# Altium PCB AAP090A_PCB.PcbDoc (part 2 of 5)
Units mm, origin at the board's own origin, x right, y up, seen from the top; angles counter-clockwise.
Board outline 160 x 130 mm, 4 copper layers (Top Layer, Signal Layer 1, Signal Layer 2, Bottom Layer), stack 1.567 mm thick; 507 components, 275 nets, 1462 pads, 1041 vias.
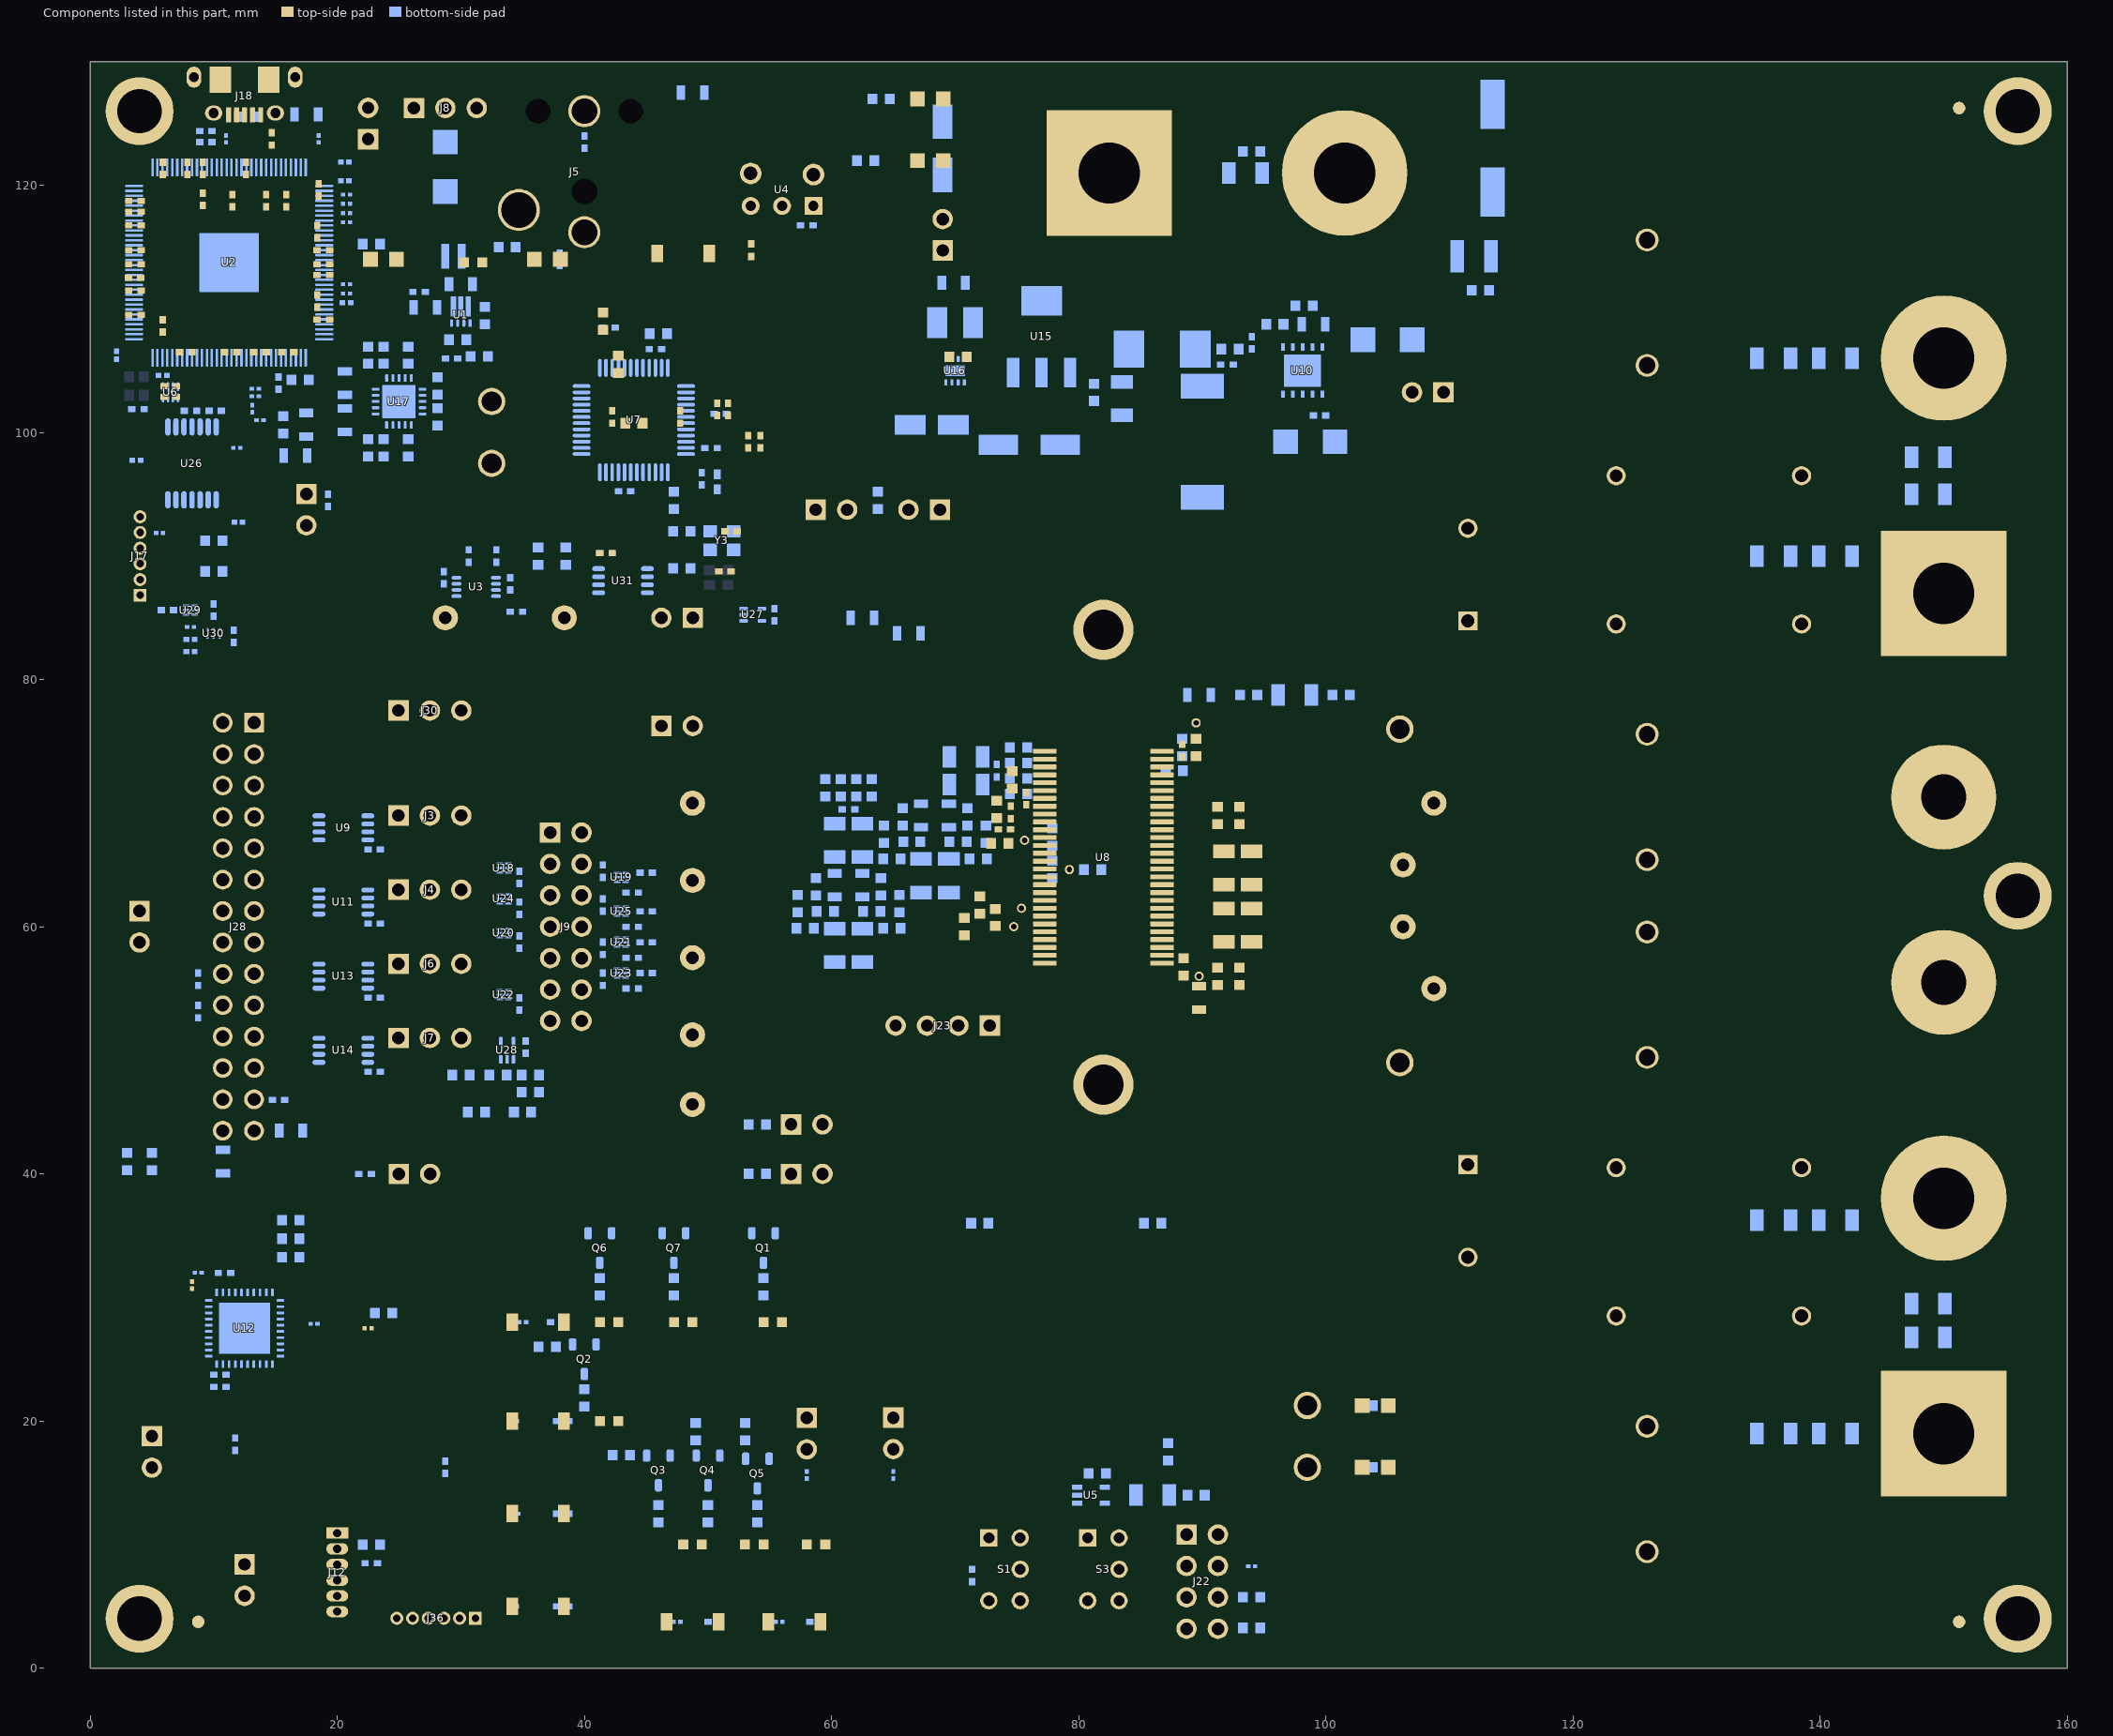
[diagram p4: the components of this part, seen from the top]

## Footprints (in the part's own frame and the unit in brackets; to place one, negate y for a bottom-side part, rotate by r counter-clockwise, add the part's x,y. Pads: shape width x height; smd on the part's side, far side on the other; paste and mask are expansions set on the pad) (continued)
DKQ0056A [mm] "SOP, 56-Leads, Body 18.415x7.49mm, Pitch 0.635mm"
  rrect25% 1.9x0.4 smd: 1(-4.75,8.572) 2(-4.75,7.938) 3(-4.75,7.302) 4(-4.75,6.667) 5(-4.75,6.032) 6(-4.75,5.397) 7(-4.75,4.763) 8(-4.75,4.127) 9(-4.75,3.492) 10(-4.75,2.857) 11(-4.75,2.222) 12(-4.75,1.587) 13(-4.75,0.953) 14(-4.75,0.318) 15(-4.75,-0.318) 16(-4.75,-0.953) 17(-4.75,-1.587) 18(-4.75,-2.222) 19(-4.75,-2.857) 20(-4.75,-3.492) 21(-4.75,-4.127) 22(-4.75,-4.763) 23(-4.75,-5.397) 24(-4.75,-6.032) 25(-4.75,-6.667) 26(-4.75,-7.302) 27(-4.75,-7.938) 28(-4.75,-8.572) 29(4.75,-8.572) 30(4.75,-7.938) 31(4.75,-7.302) 32(4.75,-6.667) 33(4.75,-6.032) 34(4.75,-5.397) 35(4.75,-4.763) 36(4.75,-4.127) 37(4.75,-3.492) 38(4.75,-2.857) 39(4.75,-2.222) 40(4.75,-1.587) 41(4.75,-0.953) 42(4.75,-0.318) 43(4.75,0.318) 44(4.75,0.953) 45(4.75,1.587) 46(4.75,2.222) 47(4.75,2.857) 48(4.75,3.492) 49(4.75,4.127) 50(4.75,4.763) 51(4.75,5.397) 52(4.75,6.032) 53(4.75,6.667) 54(4.75,7.302) 55(4.75,7.938) 56(4.75,8.572)
  silkscreen extent -5.55,-9.2 3.74,9.2, body extent -5.19,-9.21 5.19,9.21, height 2.3
DQM0008A [mm] "TI"
  rrect50% 0.7x0.2 smd: 1(-0.45,0.6) 2(-0.45,0.2) 3(-0.45,-0.2) 4(-0.45,-0.6) 5(0.45,-0.6) 6(0.45,-0.2) 7(0.45,0.2) 8(0.45,0.6)
  silkscreen extent -0.72,-1.02 0.72,1.02, body extent -0.6,-0.9 0.6,0.9, height 0.5
DRL0005A [mm] "SOTFL, 5-Flat Leads, Body 1.2x1.6x0.6mm, Pitch 0.5mm, TI recommended"
  rrect33% 0.67x0.3 smd: 1(-0.74,0.5) 2(-0.74,0) 3(-0.74,-0.5) 4(0.74,-0.5) 5(0.74,0.5)
  silkscreen extent -0.9,-0.95 0.5,0.95, body extent -0.85,-0.85 0.85,0.85, height 0.62
DRY0006A [mm] "PSON, 6-Leads, Body 1x1.45mm, Pitch 0.5mm, TI Recommended"
  rect 0.35x0.2 smd: 1(-0.275,0.5)
  rect 0.3x0.2 smd: 2(-0.3,0) 3(-0.3,-0.5) 4(0.3,-0.5) 5(0.3,0) 6(0.3,0.5)
  silkscreen extent -0.5,-0.85 0.2,0.85, body extent -0.53,-0.75 0.53,0.75, height 0.61
DSF0006A [mm] "TI recommended land pattern"
  rect 0.53x0.2 smd paste-0.1 mask+0.038: 1(-0.34,0.35) 2(-0.34,0) 3(-0.34,-0.35) 4(0.34,-0.35) 5(0.34,0) 6(0.34,0.35)
  silkscreen extent -0.85,0.63 -0.75,0.72, body extent -0.52,-0.52 0.52,0.52, height 0.4
DSG0008A [mm] "SON, 8-Leads, Body 2x2mm, Pitch 0.5mm, Thermal Pad 1.6x0.9mm, TI Recommended"
  rrect40% 0.5x0.25 smd: 1(-0.95,0.75) 2(-0.95,0.25) 3(-0.95,-0.25) 4(-0.95,-0.75) 5(0.95,-0.75) 6(0.95,-0.25) 7(0.95,0.25) 8(0.95,0.75)
  rrect11% 0.9x1.6 smd paste-0.45: 9(0,0)
  silkscreen extent -1.07,-1.15 1.07,1.15, body extent -1.05,-1.05 1.05,1.05, height 0.8
FC_1800x3550 [mm] "TH, 2-Leads, Dia 18mm, Lead Spacing 7.5mm"
  rect 1.55x1.55 hole 1.05: 1(-3.75,0)
  round 1.55 hole 1.05: 2(3.75,0)
  silkscreen extent -9.25,-9.25 9.25,9.25, body extent -9.18,-9.23 9.22,9.24, height 37.01
FCC_disclaimer [mm]
Fiducial10-20 [mm]
  round 1 smd mask+0.5: 1(0,0)
  Top Layer keep-out circle w1.178: c0,0 r0.5
HARWIN_S1911-46R [mm] "HARWIN"
  rect 2.48x3 smd mask+0.102: 1(-2.69,0) 2(2.69,0)
  silkscreen extent -0.5,-1.5 0.5,1.5, body extent -3.42,-1.25 3.43,1.26, height 0.99
Keystone5001 [mil] "For Keystone 500x miniature loop terminals"
  round 80 hole 40: 1(0,0)
  silkscreen extent -52,-52 52,52, body extent -49,-49 49,49, height 182
Keystone5003 [mil] "For Keystone 500x miniature loop terminals"
  round 80 hole 40: 1(0,0)
  silkscreen extent -52,-52 52,52, body extent -49,-49 49,49, height 182
Keystone5010 [mil] "Keystone Multipurpose loops"
  round 87 hole 63: 1(0,0)
  silkscreen extent -70,-70 70,70, body extent -63,-63 63,62, height 319
Keystone5011 [mil] "Keystone Multipurpose loops"
  round 87 hole 63: 1(0,0)
  silkscreen extent -70,-70 70,70, body extent -63,-63 63,62, height 319
Keystone5128 [mil] "Keystone Multipurpose loops"
  round 87 hole 63: 1(0,0)
  silkscreen extent -70,-70 70,70, body extent -63,-63 63,62, height 319
Keystone24438 [mil] "Standoff, Aluminium, M3x0.5mm, L 25 mm"
  round 1 on Mech4: 0(0,0)
  body extent -98,-114 98,114, height 984
Keystone_971 [mm] "PC Mount Phono Jack-Red, TH"
  round 2.6 hole 2.08: 1(0,0) 3(9.8,0)
  round 3.4 hole 2.87: 4(8,-5.3)
  round 0 hole 1.98 unplated: M1(0,3.745) M2(0,-3.745)
  round 0 hole 2.08 unplated: M3(6.5,0)
  silkscreen extent -3.99,-5.01 10.03,5.01, body extent -13.31,-5.44 10.05,5, height 13.02
Keystone_7007 [mm] "KEYSTONE"
  round 8.5 hole 3.658: 1(0,0)
  silkscreen extent -4.8,-4.8 4.8,4.8, body extent -5.71,-5.66 5.67,5.72, height 26.48
"LB Q39G_BLUE" [mm] "OSRAM"
  rect 0.8x0.8 smd: 1(-0.75,0) 2(0.75,0)
  silkscreen extent 1.3,-0.5 1.52,0.5, body extent -0.85,-0.45 0.85,0.45, height 0.4
LED_LTST-C170_Red [mm] "LITE-ON"
  rect 1.2x1.2 smd: 1(-1.05,0) 2(1.05,0)
  silkscreen extent -1.6,-1 2.2,1, body extent -1.05,-0.67 1.05,0.67, height 1.1
LED_LTST-C171 [mm] "LITE-ON"
  rect 1.2x1.2 smd: 1(-1.05,0) 2(1.05,0)
  silkscreen extent -1.6,-1 2.2,1, body extent -1.05,-0.67 1.05,0.67, height 0.8
LED_LTST-C190_Red [mm] "Lite-On"
  rect 0.8x0.8 smd: 1(-0.75,0) 2(0.75,0)
  silkscreen extent -1.1,-0.8 1.8,0.8, body extent -0.85,-0.45 0.85,0.45, height 0.9
LTST-C170KFKT_Orange [mm] "LITE-ON"
  rect 1.2x1.2 smd: 1(-1.05,0) 2(1.05,0)
  silkscreen extent -1.6,-1 2.2,1, body extent -1.05,-0.67 1.05,0.67, height 1.1
LTST-C170TBKT_Blue [mm] "LITE-ON"
  rect 1.2x1.2 smd: 1(-1.05,0) 2(1.05,0)
  silkscreen extent -1.6,-1 2.2,1, body extent -1.05,-0.67 1.05,0.67, height 1.2
MA5173 [mm] "TH, 2-Leads, Body 28.6x12.3mm, Pin Spacing 10.15mm"
  round 1.85 hole 1.35: 1(-5.075,0) 2(5.075,0)
  silkscreen extent -6.15,-14.3 6.15,14.3, body extent -6.15,-14.3 6.15,14.3, height 28.6
Mill-Max_851-XX-006-10-001000 [mil] "Mill-Max"
  rect 36x70 hole 26: 1(125,0)
  oval 36x70 hole 26: 2(75,0) 3(25,0) 4(-25,0) 5(-75,0) 6(-125,0)
  silkscreen extent -162,-50 177,50, body extent -160,-45 160,45, height 162
MP04A_N [mm] "SOT223, 4-Leads, Body 6.5x3.5mm, Pitch 2.3mm, Lead Span 7mm, IPC Medium Density"
  rect 2.4x1 smd: 1(-2.9,2.3) 2(-2.9,0) 3(-2.9,-2.3)
  rect 2.4x3.3 smd: 4(2.9,0)
  silkscreen extent -3.02,-3.35 1.4,3.48, body extent -1.85,-3.35 1.85,3.35, height 1.8
Pb-Free_Overlay_Medium [mm]
  silkscreen extent -2.41,-2.41 2.41,2.41
PBC03SAAN [mm] "Sullins 100mil, 1x3, 230 mil above insulator"
  rect 1.65x1.65 hole 1.016: 1(-2.54,0)
  round 1.65 hole 1.016: 2(0,0) 3(2.54,0)
  silkscreen extent -3.81,-1.27 3.81,1.27, body extent -3.81,-1.27 3.81,1.27, height 8.38
PFB0048A_N [mm] "Thin QFP, 48-Leads, Body 7x7mm, Pitch 0.5mm, IPC Medium Density"
  oval 1.45x0.3 smd: 1(-4.225,2.75) 2(-4.225,2.25) 3(-4.225,1.75) 4(-4.225,1.25) 5(-4.225,0.75) 6(-4.225,0.25) 7(-4.225,-0.25) 8(-4.225,-0.75) 9(-4.225,-1.25) 10(-4.225,-1.75) 11(-4.225,-2.25) 12(-4.225,-2.75) 25(4.225,-2.75) 26(4.225,-2.25) 27(4.225,-1.75) 28(4.225,-1.25) 29(4.225,-0.75) 30(4.225,-0.25) 31(4.225,0.25) 32(4.225,0.75) 33(4.225,1.25) 34(4.225,1.75) 35(4.225,2.25) 36(4.225,2.75)
  oval 0.3x1.45 smd: 13(-2.75,-4.225) 14(-2.25,-4.225) 15(-1.75,-4.225) 16(-1.25,-4.225) 17(-0.75,-4.225) 18(-0.25,-4.225) 19(0.25,-4.225) 20(0.75,-4.225) 21(1.25,-4.225) 22(1.75,-4.225) 23(2.25,-4.225) 24(2.75,-4.225) 37(2.75,4.225) 38(2.25,4.225) 39(1.75,4.225) 40(1.25,4.225) 41(0.75,4.225) 42(0.25,4.225) 43(-0.25,4.225) 44(-0.75,4.225) 45(-1.25,4.225) 46(-1.75,4.225) 47(-2.25,4.225) 48(-2.75,4.225)
  silkscreen extent -4.17,-2.75 2.75,3.57, body extent -4.5,-4.5 4.5,4.5, height 1.07
PLR135_T10 [mm] "EVERLIGHT"
  rect 1.45x1.45 hole 0.813: 1(2.54,-4.67)
  round 1.45 hole 0.813: 2(0,-4.67) 3(-2.54,-4.67)
  round 1.75 hole 1.092: 4(2.54,-2.13) 5(-2.54,-2.04)
  silkscreen extent -5.05,-6.93 5.05,6.95, body extent -5,-6.9 5,6.9, height 10.3
Pomona_6883 [mil] "Dual Binding Posts with Base, 2x1, TH"
  rect 400x400 hole 195: 1(-375,0)
  round 400 hole 195: 2(375,0)
  silkscreen extent -690,-344 690,315, body extent -690,-315 690,315, height 1354
PW0014A_N [mm] "TSOP, 14-Leads, Body 5x4.4mm, Pitch 0.65mm, IPC Medium Density"
  oval 1.4x0.45 smd: 1(-2.95,1.95) 2(-2.95,1.3) 3(-2.95,0.65) 4(-2.95,0) 5(-2.95,-0.65) 6(-2.95,-1.3) 7(-2.95,-1.95) 8(2.95,-1.95) 9(2.95,-1.3) 10(2.95,-0.65) 11(2.95,0) 12(2.95,0.65) 13(2.95,1.3) 14(2.95,1.95)
  silkscreen extent -3.4,-2.55 1.85,2.55, body extent -3.21,-2.5 3.21,2.5, height 1
RHA0040B [mm] "QFN, 40-Leads, Body 6x6mm, Pitch 0.5mm, Thermal Pad 4.15 x 4.15mm, TI Recommended"
  rrect45% 0.6x0.22 smd mask+0.07: 1(-2.9,2.25) 2(-2.9,1.75) 3(-2.9,1.25) 4(-2.9,0.75) 5(-2.9,0.25) 6(-2.9,-0.25) 7(-2.9,-0.75) 8(-2.9,-1.25) 9(-2.9,-1.75) 10(-2.9,-2.25) 21(2.9,-2.25) 22(2.9,-1.75) 23(2.9,-1.25) 24(2.9,-0.75) 25(2.9,-0.25) 26(2.9,0.25) 27(2.9,0.75) 28(2.9,1.25) 29(2.9,1.75) 30(2.9,2.25)
  rrect45% 0.22x0.6 smd mask+0.07: 11(-2.25,-2.9) 12(-1.75,-2.9) 13(-1.25,-2.9) 14(-0.75,-2.9) 15(-0.25,-2.9) 16(0.25,-2.9) 17(0.75,-2.9) 18(1.25,-2.9) 19(1.75,-2.9) 20(2.25,-2.9) 31(2.25,2.9) 32(1.75,2.9) 33(1.25,2.9) 34(0.75,2.9) 35(0.25,2.9) 36(-0.25,2.9) 37(-0.75,2.9) 38(-1.25,2.9) 39(-1.75,2.9) 40(-2.25,2.9)
  rrect9% 1.17x1.17 on Bottom Paste: 41(-1.37,-1.37) 41(-1.37,0) 41(-1.37,1.37) 41(0,-1.37) 41(0,0) 41(0,1.37) 41(1.37,-1.37) 41(1.37,0) 41(1.37,1.37)
  rrect2% 4.15x4.15 smd paste-2.1: 41(0,0)
  silkscreen extent -3.22,-3.22 3.22,3.22, body extent -3,-3 3,3, height 1
RLT0007A [mm] "TI"
  rect 0.6x0.25 smd paste-0.2: 1(-0.9,0.75)
  oval 0.6x0.25 smd paste-0.2: 2(-0.9,0.25) 3(-0.9,-0.25) 4(-0.9,-0.75)
  rect 1.64x0.44 smd paste-0.22 mask-0.07: 5(0.45,-0.6) 6(0.45,0) 7(0.45,0.6)
  silkscreen extent -1.1,-1.15 1.1,1.15, body extent -1,-1 1,1, height 1
RTJ0020D [mm] "QFN, 20-Leads, Body 4x4mm, Pitch 0.5mm, Thermal Pad 2.7x2.7mm, TI Recommended"
  rrect42% 0.6x0.24 smd: 1(-1.9,1) 2(-1.9,0.5) 3(-1.9,0) 4(-1.9,-0.5) 5(-1.9,-1) 11(1.9,-1) 12(1.9,-0.5) 13(1.9,0) 14(1.9,0.5) 15(1.9,1)
  rrect42% 0.24x0.6 smd: 6(-1,-1.9) 7(-0.5,-1.9) 8(0,-1.9) 9(0.5,-1.9) 10(1,-1.9) 16(1,1.9) 17(0.5,1.9) 18(0,1.9) 19(-0.5,1.9) 20(-1,1.9)
  rrect8% 1.19x1.19 on Bottom Paste: 21(-0.695,-0.695) 21(-0.695,0.695) 21(0.695,-0.695) 21(0.695,0.695)
  rrect4% 2.7x2.7 smd paste-1.4: 21(0,0)
  silkscreen extent -2.22,-2.22 2.23,2.22, body extent -2.07,-2.07 2.08,2.08, height 0.8
SDC10A [mm] "SON, 10-Leads, Body 4x4 mm, Pitch 0.8mm, NSC Recommended"
  rect 0.6x0.3 smd paste-0.15 mask+0.051: 1(-1.9,1.6) 2(-1.9,0.8) 3(-1.9,0) 4(-1.9,-0.8) 5(-1.9,-1.6) 6(1.9,-1.6) 7(1.9,-0.8) 8(1.9,0) 9(1.9,0.8) 10(1.9,1.6)
  rect 2.6x3 smd paste-1.3 mask+0.051: 11(0,0)
  silkscreen extent -3.02,-2.2 2.35,2.23, body extent -2.05,-2.05 2.05,2.05, height 0.8
SM_RADIAL_B [mm] "4 x 5.8mm:  Panasonic B"
  rect 2.5x1.6 smd: 1(-1.75,0) 2(1.75,0)
  silkscreen extent -2.24,-2.25 2.25,2.25, body extent -2.25,-2.25 2.25,2.25, height 6.1
SM_RADIAL_C [mm] "5 x 5.8mm:  Panasonic C"
  rect 2.8x1.6 smd: 1(-2.15,0) 2(2.15,0)
  silkscreen extent -2.75,-2.75 2.75,2.75, body extent -2.75,-2.75 2.75,2.75, height 6.1
SM_RADIAL_D [mm] "6.3 x 5.8mm:  Panasonic D"
  rect 3.2x1.6 smd: 1(-2.5,0) 2(2.5,0)
  silkscreen extent -3.4,-3.4 3.4,3.4, body extent -3.4,-3.4 3.4,3.4, height 6.1
SM_RADIAL_F [mm] "8 x 10.2mm:  Panasonic F"
  rect 4x2 smd: 1(-3.55,0) 2(3.55,0)
  silkscreen extent -4.25,-4.25 4.25,4.25, body extent -4.25,-4.25 4.25,4.25, height 10.5
SMA [mm] "Molded Diode, 2-Leads, Body 4.3x2.6mm, IPC Medium Density, based on OnSemi component dimensions and land pattern"
  rect 2x2 smd: 1(-2,0) 2(2,0)
  silkscreen extent -3.66,-1.57 2.79,1.57, body extent -2.6,-1.3 2.6,1.3, height 2.42
SNT-100-BK-G#1 [mil] "Samtec STEP model"
  round 1 on Mech4: 0(0,0)
  body extent -100,-50 100,50, height 344
SNT-100-BK-G#2 [mil] "Samtec STEP model"
  round 1 on Mech3: 0(0,0)
  body extent -100,-50 100,50, height 344
SOT-23 [mm] "SOT23, 3-Leads, Body 2.9x1.3mm, Pitch 0.95mm, Lead Span 2.5mm, IPC Medium Density"
  rrect50% 1x0.6 smd: 1(-1.2,0.95) 2(-1.2,-0.95) 3(1.2,0)
  silkscreen extent -1.62,-1.5 0.7,1.5, body extent -1.16,-1.45 1.21,1.45, height 1
SULLINS_LPPB061NGCN-RC [mm] "SULLINS"
  rect 1.05x1.05 hole 0.61: 1(3.175,2.54)
  round 1.05 hole 0.61: 2(1.905,2.54) 3(0.635,2.54) 4(-0.635,2.54) 5(-1.905,2.54) 6(-3.175,2.54)
  silkscreen extent -4,-2.37 4.03,2, body extent -4,-2.36 4,2.59, height 2.16
Sullins_PBC02SAAN [mm] "Sullins 100mil, 1x2, 230 mil above insulator"
  rect 1.65x1.65 hole 1.016: 1(0,1.27)
  round 1.65 hole 1.016: 2(0,-1.27)
  silkscreen extent -1.37,-2.54 1.27,3.1, body extent -1.27,-2.54 1.27,2.54, height 8.38
SW_200USP1T1A1M2 [mm] "TH, 5-Leads, Body 7x4.5mm, Pitch 2.54mm"
  rect 1.4x1.4 hole 0.9: 1(-1.27,2.54)
  round 1.4 hole 0.9: 3(-1.27,-2.54) 4(1.27,2.54) 5(1.27,0) 6(1.27,-2.54)
  silkscreen extent -2.7,-3.63 2.38,3.63, body extent -2.37,-3.62 2.38,3.63, height 11.13
SW_TL1015AF160QG [mm] "E-Switch"
  rect 0.95x1.4 smd: 1(-2.1,0) 2(2.1,0)
  silkscreen extent -2,-1.5 2,1.5, body extent -2.3,-1.5 2.3,1.5, height 2
TI_Stacked_Overlay_Small [mm]
  silkscreen extent -10.63,-2.49 10.63,2.49
TP_H045P075 [mm] "TP_H0.45P0.75"
  round 0.75 hole 0.45: 1(0,0)
TQFP-128 [mm] "TQFP, 128-Leads, Body 14x14mm, Pitch 0.4mm"
  rrect50% 1.45x0.2 smd: 1(-7.7,6.2) 2(-7.7,5.8) 3(-7.7,5.4) 4(-7.7,5) 5(-7.7,4.6) 6(-7.7,4.2) 7(-7.7,3.8) 8(-7.7,3.4) 9(-7.7,3) 10(-7.7,2.6) 11(-7.7,2.2) 12(-7.7,1.8) 13(-7.7,1.4) 14(-7.7,1) 15(-7.7,0.6) 16(-7.7,0.2) 17(-7.7,-0.2) 18(-7.7,-0.6) 19(-7.7,-1) 20(-7.7,-1.4) 21(-7.7,-1.8) 22(-7.7,-2.2) 23(-7.7,-2.6) 24(-7.7,-3) 25(-7.7,-3.4) 26(-7.7,-3.8) 27(-7.7,-4.2) 28(-7.7,-4.6) 29(-7.7,-5) 30(-7.7,-5.4) 31(-7.7,-5.8) 32(-7.7,-6.2) 65(7.7,-6.2) 66(7.7,-5.8) 67(7.7,-5.4) 68(7.7,-5) 69(7.7,-4.6) 70(7.7,-4.2) 71(7.7,-3.8) 72(7.7,-3.4) 73(7.7,-3) 74(7.7,-2.6) 75(7.7,-2.2) 76(7.7,-1.8) 77(7.7,-1.4) 78(7.7,-1) 79(7.7,-0.6) 80(7.7,-0.2) 81(7.7,0.2) 82(7.7,0.6) 83(7.7,1) 84(7.7,1.4) 85(7.7,1.8) 86(7.7,2.2) 87(7.7,2.6) 88(7.7,3) 89(7.7,3.4) 90(7.7,3.8) 91(7.7,4.2) 92(7.7,4.6) 93(7.7,5) 94(7.7,5.4) 95(7.7,5.8) 96(7.7,6.2)
  rrect50% 0.2x1.45 smd: 33(-6.2,-7.7) 34(-5.8,-7.7) 35(-5.4,-7.7) 36(-5,-7.7) 37(-4.6,-7.7) 38(-4.2,-7.7) 39(-3.8,-7.7) 40(-3.4,-7.7) 41(-3,-7.7) 42(-2.6,-7.7) 43(-2.2,-7.7) 44(-1.8,-7.7) 45(-1.4,-7.7) 46(-1,-7.7) 47(-0.6,-7.7) 48(-0.2,-7.7) 49(0.2,-7.7) 50(0.6,-7.7) 51(1,-7.7) 52(1.4,-7.7) 53(1.8,-7.7) 54(2.2,-7.7) 55(2.6,-7.7) 56(3,-7.7) 57(3.4,-7.7) 58(3.8,-7.7) 59(4.2,-7.7) 60(4.6,-7.7) 61(5,-7.7) 62(5.4,-7.7) 63(5.8,-7.7) 64(6.2,-7.7) 97(6.2,7.7) 98(5.8,7.7) 99(5.4,7.7) 100(5,7.7) 101(4.6,7.7) 102(4.2,7.7) 103(3.8,7.7) 104(3.4,7.7) 105(3,7.7) 106(2.6,7.7) 107(2.2,7.7) 108(1.8,7.7) 109(1.4,7.7) 110(1,7.7) 111(0.6,7.7) 112(0.2,7.7) 113(-0.2,7.7) 114(-0.6,7.7) 115(-1,7.7) 116(-1.4,7.7) 117(-1.8,7.7) 118(-2.2,7.7) 119(-2.6,7.7) 120(-3,7.7) 121(-3.4,7.7) 122(-3.8,7.7) 123(-4.2,7.7) 124(-4.6,7.7) 125(-5,7.7) 126(-5.4,7.7) 127(-5.8,7.7) 128(-6.2,7.7)
  rrect2% 4.8x4.8 smd paste-4.8: 129(0,0)
  silkscreen extent -7.1,-7.1 7.1,7.1, body extent -7,-7 7,7, height 1.2
TXC_TD [mm] "SMD, 4-Leads, Body 2x2.5mm"
  rect 1x1.1 smd: 1(-0.75,0.95) 2(-0.75,-0.95) 3(0.75,-0.95) 4(0.75,0.95)
  silkscreen extent -1.74,0.89 -1.61,1.01, body extent -1.1,-1.35 1.1,1.35, height 0.81
VLCF4020 [mm] "TDK"
  rect 1.6x2.5 smd: 1(-1.45,0) 2(1.45,0)
  Top Layer region: -0.65,1.95 -1.55,1.95 -2.25,1.25 -2.25,1.15 -0.65,1.15
  Top Layer region: -0.65,-1.95 -1.55,-1.95 -2.25,-1.25 -2.25,-1.15 -0.65,-1.15
  Top Layer region: 0.65,1.95 1.55,1.95 2.25,1.25 2.25,1.15 0.65,1.15
  Top Layer region: 0.65,-1.95 1.55,-1.95 2.25,-1.25 2.25,-1.15 0.65,-1.15
  silkscreen extent -0.4,-2.1 0.4,2.1, body extent -2.05,-2.05 2.05,2.05, height 2
VLS2012ET [mm] "TDK"
  rect 0.65x2 smd: 1(-0.675,0) 2(0.675,0)
  silkscreen extent -0.15,-1.15 0.15,1.15, body extent -1.05,-1.05 1.05,1.05, height 1.2
WE-PD_1050 [mm] "WERTH"
  rect 2x3.5 smd: 1(-4.5,0) 2(4.5,0)
  silkscreen extent -5,-5 5,5, body extent -5,-5 5,5, height 4.75

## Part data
C1 C3 C92 C124 C125: "CAP, CERM, 22 µF, 10 V, +/- 20%, X7R, 0805", Cap_Case=0805, Manufacturer=MuRata, Supplier Part Number 1=81-GRM21BZ71A226ME5L, TempCo=X7R, Tolerance_%=20, Value1=Unknown, Value2=10V, ValueDisplayed=22µF
C2 C60 C71 C87 C91 C93: "CAP, CERM, 10 µF, 10 V, +/- 20%, X5R, 0603", Cap_Case=0603, Manufacturer=MuRata, TempCo=X5R, Tolerance_%=20, Value1=Unknown, Value2=10V, ValueDisplayed=10µF
C4 C63 C65 C95 C107: "CAP, CERM, 1 µF, 16 V, +/- 10%, X7R, 0603", Cap_Case=0603, Manufacturer=MuRata, Supplier Part Number 1=490-3900-1-ND, TempCo=X7R, Tolerance_%=10, Value1="0.011 ohm", Value2=16V, ValueDisplayed=1µF
C5 C8 C11 C14: "CAP, CERM, 10 µF, 16 V, +/- 10%, X7R, 1206", Cap_Case=1206, Manufacturer=MuRata, Supplier Part Number 1=490-3911-1-ND, TempCo=X7R, Tolerance_%=10, Value1=Unknown, Value2=16V, ValueDisplayed=10µF
C6 C9 C12 C15: library part GRM1885C1H221JA01D, "CAP, CERM, 220 pF, 50 V,+/- 5%, C0G/NP0, 0603", Cap_Case=0603, Manufacturer=MuRata, Supplier Part Number 1=490-1435-1-ND, TempCo=C0G/NP0, Tolerance_%=5, Value2=50V, ValueDisplayed=220pF
C7 C10 C13 C16: library part GRM1885C1H220JA01D, "CAP, CERM, 22 pF, 50 V, +/- 5%, C0G/NP0, 0603", Cap_Case=0603, Manufacturer=MuRata, Supplier Part Number 1=490-1411-1-ND, TempCo=C0G/NP0, Tolerance_%=5, Value1=Unknown, Value2=50V, ValueDisplayed=22pF
C17 C27 C37 C40 C45 C54 C58 C74 C80 C99 C100 C101 C102 C127 C128 C129 C130 C131 C132 C133 C134 C135 C136 C137 C138 C139 C140 C143 C144 C145 C146 C147 C148 C149: "CAP, CERM, 0.1uF, 16V, +/-10%, X7R, 0402", Cap_Case=0402, Manufacturer=MuRata, Supplier Part Number 1=490-3261-1-ND, TempCo=X7R, Tolerance_%=10, Value1=Unknown, Value2=16V, ValueDisplayed=0.1µF
C18 C19 C56 C59 C61 C69 C70 C72 C73 C88 C89 C90 C94 C108 C109 C110 C111 C112 C113 C114 C115 C116 C117 C118 C119 C120 C121 C122 C123 C151 C156: "CAP, CERM, 0.1 µF, 10 V, +/- 10%, X7R, 0402", Cap_Case=0402, Manufacturer=MuRata, Supplier Part Number 1=GRM155R71A104KA01D-ND, TempCo=X7R, Tolerance_%=10, Value1=Unknown, Value2=10V, ValueDisplayed=0.1µF
C20 C21: "CAP, CERM, 0.1 µF, 16 V, +/- 10%, X7R, 0603", Cap_Case=0603, Manufacturer=MuRata, Supplier Part Number 1=490-1532-1-ND, TempCo=X7R, Tolerance_%=10, Value1=Unknown, Value2=16V, ValueDisplayed=0.1µF
C22 C36 C44 C64 C84 C96: "CAP, CERM, 0.1 µF, 50 V, +/- 10%, X7R, 0603", Cap_Case=0603, Manufacturer=Kemet, Supplier Part Number 1=399-5089-1-ND, TempCo=X7R, Tolerance_%=10, Value1=Unknown, Value2=50V, ValueDisplayed=0.1µF
C23: "CAP, CERM, 2.2 µF, 100 V, +/- 10%, X7R, 1210", Cap_Case=1210, Manufacturer=Kemet, Supplier Part Number 1=399-5511-2-ND, TempCo=X7R, Tolerance_%=10, Value1=Unknown, Value2=100V, ValueDisplayed=2.2µF
C24 C126 C141: "CAP, CERM, 0.1 µF, 16 V, +/- 10%, X7R, 0402", Cap_Case=0402, Manufacturer=MuRata, Supplier Part Number 1=490-3261-1-ND, TempCo=X7R, Tolerance_%=10, Value1=Unknown, Value2=16V, ValueDisplayed=0.1µF
C25: "CAP, CERM, 0.1 µF, 100 V, +/- 10%, X7R, 0603", Cap_Case=0603, Manufacturer=MuRata, Supplier Part Number 1=490-6439-1-ND, TempCo=X7R, Tolerance_%=10, Value1=Unknown, Value2=100V, ValueDisplayed=0.1µF
C26: "CAP, CERM, 0.047 µF, 25 V, +/- 10%, X7R, 0402", Cap_Case=0402, Manufacturer=MuRata, Supplier Part Number 1=490-3254-1-ND, TempCo=X7R, Tolerance_%=10, Value1=Unknown, Value2=25V, ValueDisplayed=0.047µF
C28 C29 C32 C41 C42 C46 C97: "CAP, CERM, 1 µF, 100 V, +/- 10%, X7R, 1206", Cap_Case=2220, Manufacturer=MuRata, Supplier Part Number 1=490-3909-1-ND, TempCo=X7R, Tolerance_%=10, Value1=Unknown, Value2=100V, ValueDisplayed=1µF
C30 C43: library part EEU-FC1H222, "CAP, AL, 2200 µF, 50 V, +/- 20%, 0.023 ohm, TH", Cap_Case=18x35.5mm, Manufacturer=Panasonic, Supplier Part Number 1=P10335-ND, Tolerance_%=20, Value1="0.023 ohm", Value2=50V, ValueDisplayed=2200µF
C31: library part EEE-FK1J470P, "CAP, AL, 47 µF, 63 V, +/- 20%, 0.65 ohm, SMD", Cap_Case=F, Manufacturer=Panasonic, Supplier Part Number 1=PCE3823CT-ND, Tolerance_%=20, Value1="0.65 ohm", Value2=63V, ValueDisplayed=47µF
C33: "CAP, CERM, 0.01 µF, 100 V, +/- 10%, X7R, 0603", Cap_Case=0603, Manufacturer=AVX, Supplier Part Number 1=478-1205-1-ND, TempCo=X7R, Tolerance_%=10, Value1="0.098 ohm", Value2=100V, ValueDisplayed=0.01µF
C34: "CAP, CERM, 5600 pF, 50 V, +/- 10%, X7R, 0603", Cap_Case=0603, Manufacturer=MuRata, Supplier Part Number 1=490-1507-1-ND, TempCo=X7R, Tolerance_%=10, Value1=Unknown, Value2=50V, ValueDisplayed=5600pF
C35: "CAP, CERM, 4700 pF, 50 V, +/- 10%, X7R, 0603", Cap_Case=0603, Manufacturer=Kemet, Supplier Part Number 1=399-5337-1-ND, TempCo=X7R, Tolerance_%=10, Value1=Unknown, Value2=50V, ValueDisplayed=4700pF
C38: "CAP, CERM, 4.7 µF, 25 V, +/- 10%, X7R, 1206", Cap_Case=1206, Manufacturer=MuRata, Supplier Part Number 1=490-1809-1-ND, TempCo=X7R, Tolerance_%=10, Value1=Unknown, Value2=25V, ValueDisplayed=4.7µF
C39: library part EEE-FK1C470P, "CAP, AL, 47 µF, 16 V, +/- 20%, 0.36 ohm, SMD", Cap_Case=D, Manufacturer=Panasonic, Supplier Part Number 1=PCE3790CT-ND, Tolerance_%=20, Value1="0.36 ohm", Value2=16V, ValueDisplayed=47µF
C47 C67 C79 C81: "CAP, Film, 0.68 µF, 250 V, +/- 5%, TH", Cap_Case=18x9x17.5mm, Manufacturer="EPCOS Inc", Supplier Part Number 1=495-1299-ND, Tolerance_%=5, Value1=Unknown, Value2=250V, ValueDisplayed=0.68µF
C48 C49 C50 C51 C53 C57 C150: "CAP, CERM, 470 pF, 25 V, +/- 5%, C0G/NP0, 0402", Cap_Case=0402, Manufacturer=MuRata, Supplier Part Number 1=GRM1555C1E471JA01D-ND, TempCo=C0G/NP0, Tolerance_%=5, Value1=Unknown, Value2=25V, ValueDisplayed=470pF
C52: "CAP, CERM, 2200 pF, 16 V, +/- 10%, X7R, 0603", Cap_Case=0603, Manufacturer="Wurth Elektronik", Supplier Part Number 1=710-885012206036, TempCo=X7R, Tolerance_%=10, Value1=Unknown, Value2=16V, ValueDisplayed=2200pF
C55: "CAP, CERM, 1 µF, 6.3 V,+/- 20%, X5R, 0402", Cap_Case=0402, Manufacturer=MuRata, Supplier Part Number 1=490-10006-1-ND, TempCo=X5R, Tolerance_%=20, Value2=6.3V, ValueDisplayed=1µF
C62 C106: "CAP, CERM, 1000 pF, 50 V, +/- 5%, C0G/NP0, 0402", Cap_Case=0402, Manufacturer=MuRata, Supplier Part Number 1=490-3244-1-ND, TempCo=C0G/NP0, Tolerance_%=5, Value1=Unknown, Value2=50V, ValueDisplayed=1000pF
C66 C68 C76 C77: "CAP, CERM, 0.033 µF, 25 V, +/- 10%, X7R, 0603", Cap_Case=0603, Manufacturer=MuRata, Supplier Part Number 1=490-1521-1-ND, TempCo=X7R, Tolerance_%=10, Value1=Unknown, Value2=25V, ValueDisplayed=0.033µF
C75: "CAP, CERM, 2.2 µF, 10 V, +/- 10%, X5R, 0402", Cap_Case=0402, Manufacturer=TDK, Supplier Part Number 1=445-7392-1-ND, TempCo=X5R, Tolerance_%=10, Value1=Unknown, Value2=10V, ValueDisplayed=2.2µF
C78: "CAP, CERM, 0.047 µF, 50 V, +/- 10%, X7R, 0603", Cap_Case=0603, Manufacturer=MuRata, Supplier Part Number 1=490-3287-1-ND, TempCo=X7R, Tolerance_%=10, Value1=Unknown, Value2=50V, ValueDisplayed=0.047µF
C82: library part GRM155R71C104KA88D, "CAP, CERM, 0.1 µF, 16 V, +/- 10%, X7R, 0402", Cap_Case=0402, Manufacturer=MuRata, Supplier Part Number 1=490-3261-1-ND, TempCo=X7R, Tolerance_%=10, Value1=Unknown, Value2=16V, ValueDisplayed=0.1µF
C83: "CAP, CERM, 0.47 µF, 25 V, +/- 10%, X7R, 0603", Cap_Case=0603, Manufacturer=MuRata, Supplier Part Number 1=490-3291-1-ND, TempCo=X7R, Tolerance_%=10, Value1=Unknown, Value2=25V, ValueDisplayed=0.47µF
C85: library part EEE-FK1C100R, "CAP, AL, 10 µF, 16 V, +/- 20%, 1.35 ohm, SMD", Cap_Case=B, Manufacturer=Panasonic, Supplier Part Number 1=PCE3782CT-ND, Tolerance_%=20, Value1="1.35 ohm", Value2=16V, ValueDisplayed=10µF
C86: library part EEE-FK0J101UR, "CAP, AL, 100 µF, 6.3 V, +/- 20%, 0.7 ohm, SMD", Cap_Case=C, Manufacturer=Panasonic, Supplier Part Number 1=PCE3762CT-ND, Tolerance_%=20, Value1="0.7 ohm", Value2=6.3V, ValueDisplayed=100µF
C98 C103 C104 C105: library part GRM31CR72A105KA01L, "CAP, CERM, 1 µF, 100 V, +/- 10%, X7R, 1206", Cap_Case=2220, Manufacturer=MuRata, Supplier Part Number 1=490-3909-1-ND, TempCo=X7R, Tolerance_%=10, Value1=Unknown, Value2=100V, ValueDisplayed=1µF
C142: "CAP, CERM, 2.2 µF, 10 V, +/- 10%, X7R, 0603", Cap_Case=0603, Manufacturer=MuRata, Supplier Part Number 1=490-4520-1-ND, TempCo=X7R, Tolerance_%=10, Value1="0.009 ohm", Value2=10V, ValueDisplayed=2.2µF
C152 C153 C154 C155: library part GRM3195C1H102JA01D, "CAP, CERM, 1000 pF, 50 V, +/- 5%, C0G/NP0, 1206", Cap_Case=1206, Manufacturer=MuRata, Supplier Part Number 1=490-1749-1-ND, TempCo=C0G/NP0, Tolerance_%=5, Value1=Unknown, Value2=50V, ValueDisplayed=1000pF
D1: library part LTST-C170TBKT, "LED, Blue, SMD", Color=Blue, Manufacturer=Lite-On, Supplier Part Number 1=160-1579-1-ND, Value1=W, Value2=3.3V
D2 D5 D6 D7 D8 D15 D16: library part "LB Q39G-L2N2-35-1", "LED, Blue, SMD", Color=blue, Manufacturer=OSRAM, Supplier Part Number 1=475-2816-1-ND, Value1=W, Value2=2.85V
D3 D13 D14: library part LTST-C171GKT, "LED, Green, SMD", Color=green, Manufacturer=Lite-On, Supplier Part Number 1=160-1423-1-ND, Value1=W, Value2=2.1V
D4: library part LTST-C190CKT, "LED, Red, SMD", Color=red, Manufacturer=Lite-On, Power_TotalModule=0.0625, Supplier Part Number 1=160-1181-1-ND, Value1=0.0625W, Value2=2V
D9: library part LTST-C170KFKT, "LED, Orange, SMD", Color=orange, Manufacturer=Lite-On, Supplier Part Number 1=160-1413-1-ND, Value1=W, Value2=2V
D10: library part LTST-C170KRKT, "LED, Red, SMD", Color=red, Manufacturer=Lite-On, Supplier Part Number 1=160-1415-1-ND, Value1=W, Value2=2V
D11: "Diode, Schottky, 100 V, 3 A, SMA", Manufacturer="Micro Commercial Components", Supplier Part Number 1=SK310A-TPCT-ND, Value1=3A, Value2=0.85V
D12 D17: "Diode, Schottky, 100 V, 1 A, SMA", Manufacturer="Diodes Inc.", Supplier Part Number 1=B1100-FDICT-ND, Value1=1A, Value2=0.79V
FID1 FID2 FID3 FID4 FID5 FID6: "Fiducial mark.  There is nothing to buy or mount.", Manufacturer=N/A
H1: library part CMP-0078258-2, "Heat Sink, 36x78x36.5mm", Manufacturer="Advanced Thermal Solutions"
H2 H3 H4 H5 H10: library part "RM3X8MM 2701", "MACHINE SCREW PAN PHILLIPS M3", Manufacturer="APM HEXSEAL", Supplier Part Number 1=335-1149-ND
H6 H7 H8 H9 H11: library part 24438, "Standoff, Hex,25mm Length, M3, Aluminum", Manufacturer=Keystone, Supplier Part Number 1=36-24438-ND
J1 J2 J11 J14 J16 J19 J20 J26 J27 J29 J31 J32 J33 J35 J37: library part PBC02SAAN, "Header, 100mil, 2x1, Gold, TH", Color=Black, Current_A=3, Manufacturer="Sullins Connector Solutions", Supplier Part Number 1=S1011E-02-ND, Voltage_V=1800
J3 J4 J6 J7 J8 J30: library part PBC03SAAN, "Header, 100mil, 3x1, Gold, TH", Manufacturer="Sullins Connector Solutions", Supplier Part Number 1=S1011E-03-ND
J5: library part 971, "RCA Jack, Red, R/A, TH", Manufacturer=Keystone, Supplier Part Number 1=36-971-ND
J9: library part SBH11-PBPC-D07-ST-BK, "Header (shrouded), 100 mil, 7x2, Gold, TH", Manufacturer="Sullins Connector Solutions", Supplier Part Number 1=S9170-ND
J10 J15 J24: library part CMP-0075104-1, "Dual Binding Posts with Base, 2x1, TH", Manufacturer="Pomona Electronics", PartNumber=6883, Supplier Part Number 1=501-1316-ND
J12: library part 851-43-006-10-001000, "Receptacle, 50mil, 6x1, Gold, TH", Manufacturer=Mill-Max, Supplier Part Number 1=ED90529-ND
J13 J21: library part 7007, "Binding Post, BLACK, TH", Manufacturer=Keystone, Shell Color=Black, Supplier Part Number 1=7007K-ND
J17 J36: library part LPPB061NGCN-RC, "Receptacle, 50mil, 6x1, Gold, R/A, TH", Manufacturer="Sullins Connector Solutions", Supplier Part Number 1=S9010E-06-ND
J18: library part CMP-0074926-1, "Connector, Receptacle, Micro-USB Type AB, R/A, Bottom Mount SMT", Manufacturer="JAE Electronics", PartNumber=DX4R205JJAR1800, Supplier Part Number 1=670-2677-1-ND
J22: "Header, 100mil, 4x2, Tin, TH", Color=Black, Current_A=3, Manufacturer="Sullins Connector Solutions", Supplier Part Number 1=S2012E-04-ND, Voltage_V=1800
J23: "Header (friction lock), 100mil, 4x1, Gold, TH", Manufacturer=Molex, Supplier Part Number 1=WM2702-ND
J25: library part CMP-0075020-1, "JUMPER TIN SMD", Manufacturer=Harwin, Supplier Part Number 1=952-1740-1-ND
J28: library part CMP-0075444-1, "Receptacle, 100mil, 14x2, Gold, TH", Manufacturer=Samtec, Supplier Part Number 1=SAM1208-14-ND
J34: "Header, 100mil, 2x1, Gold, TH", Color=Black, Current_A=3, Manufacturer="Sullins Connector Solutions", Supplier Part Number 1=S1011E-02-ND, Voltage_V=1800
L1: "Inductor, Shielded Drum Core, Ferrite, 470 nH, 2 A, 0.059 ohm, SMD", Manufacturer=TDK, Supplier Part Number 1=445-6606-1-ND, Value1="0.059 ohm", Value2=2A, ValueDisplayed=470nH
L2: "Ferrite Bead, 600 ohm @ 100MHz, 2A, 0805", Manufacturer=TDK, Supplier Part Number 1=445-2206-1-ND, Value1="0.1 ohm", Value2=2A
L3: library part CMP-0062895-1, "Inductor, Shielded, Ferrite, 2.2 uH, 1.72 A, 0.059 ohm, SMD", Manufacturer=TDK, Supplier Part Number 1=445-3182-1-ND, Value1="0.059 ohm", Value2=1.72A, ValueDisplayed=2.2uH
L4: "Ferrite Bead, 120 ohm @ 100 MHz, 0.4 A, 0402", Manufacturer=TDK, Supplier Part Number 1=445-2152-1-ND, Value1="0.18 ohm", Value2=0.4A
L5 L6 L7 L8: library part MA5173-AE, "Inductor, Toroid, Powdered Iron, 7 µH, 6.5 A, 0.0215 ohm, TH", Manufacturer=Coilcraft, Supplier Part Number 1=994-MA5173-AE, Value1="0.0215 ohm", Value2=6.5A, ValueDisplayed=7µH
L9: "Inductor, Shielded Drum Core, Ferrite, 100 µH, 1.5 A, 0.165 ohm, SMD", Manufacturer="Wurth Elektronik", Supplier Part Number 1=732-2989-1-ND, Value1="0.165 ohm", Value2=1.5A, ValueDisplayed=100µH
Logo1: library part TI_Logo, "Texas Instrument Corporate Signature"
Logo2: library part Pb-Free
Logo3: library part FCC_disclaimer, "FCC_disclaimer"
Q1 Q2 Q3 Q4 Q5 Q6 Q7: library part "MMBT2222A, Fairchild Semiconductor", "Transistor, NPN, 40 V, 0.15 A, SOT-23", Manufacturer="Fairchild Semiconductor", Supplier Part Number 1=MMBT2222AFSCT-ND, Value1="0.15 A", Value2=300
R1: "RES, 40.2 k, 1%, 0.1 W, AEC-Q200 Grade 0, 0402", Manufacturer=Panasonic, Power_W=0.1, Supplier Part Number 1=P40.2KLCT-ND, TempCo="100 ppm/C", Tolerance_%=1, Value1=1%, Value2=0.1W, Value_Code=40k2, ValueDisplayed=40.2k
R2: "RES, 1.00 M, 1%, 0.1 W, 0603", Manufacturer="Yageo America", Power_W=0.1, Supplier Part Number 1=311-1.00MHRCT-ND, TempCo="200 ppm/C", Tolerance_%=1, Value1=1%, Value2=0.1W, Value_Code=1M00, ValueDisplayed=1.00M
R3: "RES, 162 k, 1%, 0.1 W, 0603", Manufacturer="Yageo America", Power_W=0.1, Supplier Part Number 1=311-162KHRCT-ND, TempCo="200 ppm/C", Tolerance_%=1, Value1=1%, Value2=0.1W, Value_Code=162k
R4 R32 R59 R64 R65 R88: "RES, 100 k, 1%, 0.1 W, 0603", Manufacturer="Yageo America", Power_W=0.1, Supplier Part Number 1=311-100KHRCT-ND, TempCo="200 ppm/C", Tolerance_%=1, Value1=1%, Value2=0.1W, Value_Code=100k
R5 R66 R77 R90 R91 R114 R129 R144 R149 R150 R154 R155: "RES, 10.0 k, 1%, 0.05 W, 0201", Manufacturer="Yageo America", Power_W=0.05, Supplier Part Number 1=311-10.0KMCT-ND, TempCo="200 ppm/C", Tolerance_%=1, Value1=1%, Value2=0.05W, Value_Code=10k0, ValueDisplayed=10.0k
R6: "RES, 33.2 k, 1%, 0.1 W, 0603", Manufacturer="Yageo America", Power_W=0.1, Supplier Part Number 1=311-33.2KHRCT-ND, TempCo="200 ppm/C", Tolerance_%=1, Value1=1%, Value2=0.1W, Value_Code=33k2, ValueDisplayed=33.2k
R7: "RES, 10.7 k, 1%, 0.1 W, 0603", Manufacturer="Yageo America", Power_W=0.1, Supplier Part Number 1=311-10.7KHRCT-ND, TempCo="200 ppm/C", Tolerance_%=1, Value1=1%, Value2=0.1W, Value_Code=10k7, ValueDisplayed=10.7k
R8: "RES, 13.7 k, 1%, 0.1 W, 0603", Manufacturer="Yageo America", Power_W=0.1, Supplier Part Number 1=311-13.7KHRCT-ND, TempCo="200 ppm/C", Tolerance_%=1, Value1=1%, Value2=0.1W, Value_Code=13k7, ValueDisplayed=13.7k
R9: "RES, 11.0 k, 1%, 0.1 W, 0603", Manufacturer="Yageo America", Power_W=0.1, Supplier Part Number 1=311-11.0KHRCT-ND, TempCo="200 ppm/C", Tolerance_%=1, Value1=1%, Value2=0.1W, Value_Code=11k0, ValueDisplayed=11.0k
R10 R11 R12 R63 R101 R166 R167: library part ERJ-3GEY0R00V, "RES, 0, 5%, 0.1 W, 0603", Manufacturer=Panasonic, Power_W=0.1, Supplier Part Number 1=P0.0GCT-ND, TempCo="600 ppm/C", Tolerance_%=5, Value1=5%, Value2=0.1W, Value_Code=0000, ValueDisplayed=0
R13 R30 R61 R72: "RES, 0, 5%, 0.25 W, 1206", Manufacturer="Yageo America", Power_W=0.25, Supplier Part Number 1=311-0.0ERCT-ND, TempCo="200 ppm/C", Tolerance_%=5, Value1=5%, Value2=0.25W, Value_Code=0000, ValueDisplayed=0
R14 R28 R33 R68 R73: library part ERJ-6GEY0R00V, "RES, 0, 5%, 0.125 W, 0805", Manufacturer=Panasonic, Power_W=0.125, Supplier Part Number 1=P0.0ACT-ND, TempCo="600 ppm/C", Tolerance_%=5, Value1=5%, Value2=0.125W, Value_Code=0000, ValueDisplayed=0
R15 R35 R70 R96: library part RC0603FR-0718KL, "RES, 18.0 k, 1%, 0.1 W, 0603", Manufacturer="Yageo America", Power_W=0.1, Supplier Part Number 1=311-18.0KHRCT-ND, TempCo="200 ppm/C", Tolerance_%=1, Value1=1%, Value2=0.1W, Value_Code=18k0, ValueDisplayed=18.0k
R16: "RES, 33.0, 1%, 0.1 W, 0402", Manufacturer=Panasonic, Power_W=0.1, Supplier Part Number 1=P33.0LCT-ND, TempCo="100 ppm/C", Tolerance_%=1, Value1=1%, Value2=0.1W, Value_Code=33R0, ValueDisplayed=33.0
R17 R18 R21 R24 R43: "RES, 49.9, 1%, 0.063 W, 0402", Manufacturer="Yageo America", Power_W=0.063, Supplier Part Number 1=311-49.9LRCT-ND, TempCo="100 ppm/C", Tolerance_%=1, Value1=1%, Value2=0.063W, Value_Code=49R9, ValueDisplayed=49.9
R19 R46 R47 R48 R49 R57 R78 R79 R106 R108 R141: "RES, 560, 5%, 0.1 W, 0603", Manufacturer="Yageo America", Power_W=0.1, Supplier Part Number 1=311-560GRCT-ND, TempCo="100 ppm/C", Tolerance_%=5, Value1=5%, Value2=0.1W, Value_Code=560R, ValueDisplayed=560
R20 R23 R84 R110: "RES, 1.00 k, 1%, 0.0625 W, 0402", Manufacturer="Yageo America", Power_W=0.0625, Supplier Part Number 1=311-1.00KLRCT-ND, TempCo="100 ppm/C", Tolerance_%=1, Value1=1%, Value2=0.0625W, Value_Code=1k00, ValueDisplayed=1.00k
R22 R58 R81 R82 R124 R133: "RES, 4.99 k, 1%, 0.063 W, 0402", Manufacturer="Yageo America", Power_W=0.063, Supplier Part Number 1=311-4.99KLRCT-ND, TempCo="100 ppm/C", Tolerance_%=1, Value1=1%, Value2=0.063W, Value_Code=4k99, ValueDisplayed=4.99k
R25: library part RMCF0402FT10K0, "RES, 10.0 k, 1%, 0.063 W, AEC-Q200 Grade 0, 0402", Manufacturer="Stackpole Electronics Inc", Power_W=0.063, Supplier Part Number 1=RMCF0402FT10K0CT-ND, TempCo="100 ppm/C", Tolerance_%=1, Value1=1%, Value2=0.063W, Value_Code=10k0, ValueDisplayed=10.0k
R26 R27 R111: "RES, 0, 5%, 0.063 W, 0402", Manufacturer=Panasonic, Power_W=0.063, Supplier Part Number 1=P0.0JCT-ND, TempCo="600 ppm/C", Tolerance_%=5, Value1=5%, Value2=0.063W, Value_Code=0000, ValueDisplayed=0
R29 R37 R71 R97: library part RC0603FR-072KL, "RES, 2.00 k, 1%, 0.1 W, 0603", Manufacturer="Yageo America", Power_W=0.1, Supplier Part Number 1=311-2.00KHRCT-ND, TempCo="200 ppm/C", Tolerance_%=1, Value1=1%, Value2=0.1W, Value_Code=2k00, ValueDisplayed=2.00k
R31 R36 R125 R126 R127 R128 R159 R164: "RES, 0, 5%, 0.125 W, 0805", Manufacturer="Yageo America", Power_W=0.125, Supplier Part Number 1=311-0.0ARCT-ND, TempCo="200 ppm/C", Tolerance_%=5, Value1=5%, Value2=0.125W, Value_Code=0000, ValueDisplayed=0
R34: "RES, 182 k, 1%, 0.125 W, 0805", Manufacturer=Panasonic, Power_W=0.125, Supplier Part Number 1=P182KCCT-ND, TempCo="100 ppm/C", Tolerance_%=1, Value1=1%, Value2=0.125W, Value_Code=182k
R38 R39 R40 R42 R44 R45 R156: "RES, 25.5 k, 1%, 0.05 W, 0201", Manufacturer="Yageo America", Power_W=0.05, Supplier Part Number 1=YAG2538CT-ND, TempCo="200 ppm/C", Tolerance_%=1, Value1=1%, Value2=0.05W, Value_Code=25k5, ValueDisplayed=25.5k
R41 R157: "RES, 47.0 k, 1%, 0.0625 W, 0402", Manufacturer="Yageo America", Power_W=0.0625, Supplier Part Number 1=311-47.0KLRCT-ND, TempCo="100 ppm/C", Tolerance_%=1, Value1=1%, Value2=0.0625W, Value_Code=47k0, ValueDisplayed=47.0k
R50 R51 R52 R53 R105 R107 R109: "RES, 2.00 k, 1%, 0.1 W, 0603", Manufacturer="Yageo America", Power_W=0.1, Supplier Part Number 1=311-2.00KHRCT-ND, TempCo="200 ppm/C", Tolerance_%=1, Value1=1%, Value2=0.1W, Value_Code=2k00, ValueDisplayed=2.00k
R54 R55 R62 R99 R100 R102 R103 R104 R112 R113 R130 R131 R132 R134 R135 R165 R168 R169 R170: "RES, 0, 5%, 0.1 W, 0603", Manufacturer=Panasonic, Power_W=0.1, Supplier Part Number 1=P0.0GCT-ND, TempCo="600 ppm/C", Tolerance_%=5, Value1=5%, Value2=0.1W, Value_Code=0000, ValueDisplayed=0
R56: "RES, 8.06 k, 1%, 0.1 W, 0603", Manufacturer="Yageo America", Power_W=0.1, Supplier Part Number 1=311-8.06KHRCT-ND, TempCo="200 ppm/C", Tolerance_%=1, Value1=1%, Value2=0.1W, Value_Code=8k06, ValueDisplayed=8.06k
R60: "RES, 3.30 k, 1%, 0.1 W, 0603", Manufacturer="Yageo America", Power_W=0.1, Supplier Part Number 1=311-3.30KHRCT-ND, TempCo="200 ppm/C", Tolerance_%=1, Value1=1%, Value2=0.1W, Value_Code=3k30, ValueDisplayed=3.30k
R67 R69 R86 R95 R98: "RES, 499, 1%, 0.1 W, 0603", Manufacturer="Yageo America", Power_W=0.1, Supplier Part Number 1=311-499HRCT-ND, TempCo="200 ppm/C", Tolerance_%=1, Value1=1%, Value2=0.1W, Value_Code=499R, ValueDisplayed=499
R74: "RES, 22.0 k, 1%, 0.1 W, 0603", Manufacturer="Yageo America", Power_W=0.1, Supplier Part Number 1=311-22.0KHRCT-ND, TempCo="200 ppm/C", Tolerance_%=1, Value1=1%, Value2=0.1W, Value_Code=22k0, ValueDisplayed=22.0k
R75: "RES, 30.0 k, 1%, 0.1 W, 0603", Manufacturer="Yageo America", Power_W=0.1, Supplier Part Number 1=311-30.0KHRCT-ND, TempCo="200 ppm/C", Tolerance_%=1, Value1=1%, Value2=0.1W, Value_Code=30k0, ValueDisplayed=30.0k
R76: "RES, 20.0 k, 1%, 0.1 W, 0603", Manufacturer="Yageo America", Power_W=0.1, Supplier Part Number 1=311-20.0KHRCT-ND, TempCo="200 ppm/C", Tolerance_%=1, Value1=1%, Value2=0.1W, Value_Code=20k0, ValueDisplayed=20.0k
R80 R92 R121 R145: "RES, 10.0 k, 1%, 0.1 W, 0402", Manufacturer=Panasonic, Power_W=0.1, Supplier Part Number 1=P10.0KLCT-ND, TempCo="100 ppm/C", Tolerance_%=1, Value1=1%, Value2=0.1W, Value_Code=10k0, ValueDisplayed=10.0k
R83 R142 R143 R146 R151 R152 R153: "RES, 33.2, 1%, 0.05 W, 0201", Manufacturer="Yageo America", Power_W=0.05, Supplier Part Number 1=YAG2608CT-ND, TempCo="200 ppm/C", Tolerance_%=1, Value1=1%, Value2=0.05W, Value_Code=33R2, ValueDisplayed=33.2
R85: "RES, 1.50 k, 1%, 0.1 W, 0603", Manufacturer="Yageo America", Power_W=0.1, Supplier Part Number 1=311-1.50KHRCT-ND, TempCo="200 ppm/C", Tolerance_%=1, Value1=1%, Value2=0.1W, Value_Code=1k50, ValueDisplayed=1.50k
R87 R89 R93 R94: library part ERJ-8RQF3R3V, "RES, 3.30, 1%, 0.25 W, 1206", Manufacturer=Panasonic, Power_W=0.25, Supplier Part Number 1=P3.3RCT-ND, TempCo="200 ppm/C", Tolerance_%=1, Value1=1%, Value2=0.25W, Value_Code=3R30, ValueDisplayed=3.30
R115 R116 R117 R118: "RES, 100 k, 1%, 0.0625 W, 0402", Manufacturer="Yageo America", Power_W=0.0625, Supplier Part Number 1=311-100KLRCT-ND, TempCo="100 ppm/C", Tolerance_%=1, Value1=1%, Value2=0.0625W, Value_Code=100k
R119 R120 R122: library part ERJ-2RKF1002X, "RES, 10.0 k, 1%, 0.1 W, 0402", Manufacturer=Panasonic, Power_W=0.1, Supplier Part Number 1=P10.0KLCT-ND, TempCo="100 ppm/C", Tolerance_%=1, Value1=1%, Value2=0.1W, Value_Code=10k0, ValueDisplayed=10.0k
R123: "RES, 10.0 k, 1%, 0.063 W, AEC-Q200 Grade 0, 0402", Manufacturer="Stackpole Electronics Inc", Power_W=0.063, Supplier Part Number 1=RMCF0402FT10K0CT-ND, TempCo="100 ppm/C", Tolerance_%=1, Value1=1%, Value2=0.063W, Value_Code=10k0, ValueDisplayed=10.0k
R136 R137 R138 R139: "RES, 47.0 k, 1%, 0.05 W, 0201", Manufacturer="Yageo America", Power_W=0.05, Supplier Part Number 1=311-47KMCT-ND, TempCo="200 ppm/C", Tolerance_%=1, Value1=1%, Value2=0.05W, Value_Code=47k0, ValueDisplayed=47.0k
R140: "RES, 4.75, 1%, 0.1 W, 0603", Manufacturer="Yageo America", Power_W=0.1, Supplier Part Number 1=311-4.75HRCT-ND, TempCo="200 ppm/C", Tolerance_%=1, Value1=1%, Value2=0.1W, Value_Code=4R75, ValueDisplayed=4.75
R147: "RES, 0, 5%, 0.05 W, 0201", Manufacturer=Panasonic, Power_W=0.05, Supplier Part Number 1=P0.0AGCT-ND, TempCo="600 ppm/C", Tolerance_%=5, Value1=5%, Value2=0.05W, Value_Code=0000, ValueDisplayed=0
R148: "RES, 43.2, 1%, 0.05 W, 0201", Manufacturer="Yageo America", Power_W=0.05, Supplier Part Number 1=YAG2674CT-ND, TempCo="200 ppm/C", Tolerance_%=1, Value1=1%, Value2=0.05W, Value_Code=43R2, ValueDisplayed=43.2
R158: "RES, 51.0 k, 1%, 0.05 W, 0201", Manufacturer="Yageo America", Power_W=0.05, Supplier Part Number 1=311-51.0KMCT-ND, TempCo="200 ppm/C", Tolerance_%=1, Value1=1%, Value2=0.05W, Value_Code=51k0, ValueDisplayed=51.0k
R160 R161 R162 R163: library part ERJ-1GE0R00C, "RES, 0, 5%, 0.05 W, 0201", Manufacturer=Panasonic, Power_W=0.05, Supplier Part Number 1=P0.0AGCT-ND, TempCo="600 ppm/C", Tolerance_%=5, Value1=5%, Value2=0.05W, Value_Code=0000, ValueDisplayed=0
S1 S3: library part 200USP1T1A1M2RE, "Switch, SPDT, On-On, 2 Pos, TH", CurrentRating_mA=400, Manufacturer=E-Switch, Supplier Part Number 1=EG4915-ND
S2 S4 S5 S6 S7 S8 S9: library part TL1015AF160QG, "Switch, Tactile, SPST-NO, 0.05A, 12V, SMT", CurrentRating_mA=50, Manufacturer=E-Switch, Supplier Part Number 1=EG4344CT-ND
SH1 SH2 SH3 SH4 SH5 SH6 SH7 SH8 SH9 SH10 SH11 SH12 SH13 SH14 SH15 SH16 SH17 SH18 SH19 SH20 SH21 SH22: "Shunt, 100mil, Gold plated, Black", Alternate Manufacturer=3M, Alternate PartNumber=969102-0000-DA, Manufacturer=Samtec, Supplier Part Number 1=SNT-100-BK-G-ND
TP1 TP2 TP3 TP4 TP17 TP18 TP19 TP20 TP21 TP22: library part 5003, "Test Point, Miniature, Orange, TH", Color=Orange, Manufacturer=Keystone, Supplier Part Number 1=36-5003-ND
TP5: library part 5010, "Test Point, Multipurpose, Red, TH", Color=Red, Manufacturer=Keystone, Supplier Part Number 1=36-5010-ND
TP6: library part 5011, "Test Point, Multipurpose, Black, TH", Color=Black, Manufacturer=Keystone, Supplier Part Number 1=36-5011-ND
TP7 TP8 TP15 TP16: library part 5128, "Test Point, Multipurpose, Grey, TH", Color=Grey, Manufacturer=Keystone, Supplier Part Number 1=36-5128-ND
TP9 TP10 TP11 TP12 TP13 TP14: library part TP_H0.45P0.75, "Testpoint", Manufacturer="Texas Instruments"
TP23: library part 5001, "Test Point, Miniature, Black, TH", Color=Black, Manufacturer=Keystone, Supplier Part Number 1=36-5001-ND
U1: "3-A Step-Down Converter with Hiccup Short Circuit Protection in 2x2 QFN Package, RLT0007A", Alternate Manufacturer="Texas Instruments", Alternate PartNumber=TPS62085RLTT
U2: library part CMP-0004936-1, "IC MCU 512KB RAM, 128TQFP", Manufacturer="XMOS semiconductor", Supplier Part Number 1=880-1100-ND
U3: "TCA9406 Dual Bidirectional 1-MHz I2C-BUS and SMBus Voltage Level-Translator, 1.65 to 3.6 V, -40 to 85 degC, 8-pin US8 (DCU), Green (RoHS & no Sb/Br)", 5V Tolerant I/O=Yes, Alternate Manufacturer="Texas Instruments", Alternate PartNumber=Equivalent, Max Frequency(kHz)=1000, On-Chip Power-on-Reset=No, Rating=Catalog, Supplier Part Number 1=296-28109-2-ND
U4: library part PLR135/T10, "Photolink- Fiber Optic Receiver, TH", Manufacturer=Everlight, Supplier Part Number 1=1080-1433-ND
U5: "ULTRA-SMALL SUPPLY VOLTAGE SUPERVISORS, DCK0005A", Alternate Manufacturer="Texas Instruments"
U6: "2-BIT UNDIRECTIONAL VOLTAGE-LEVEL TRANSLATOR, DQM0008A (X2SON-8)", Alternate Manufacturer="Texas Instruments"
U7: "216 SPS High-end Combo Sample Rate Converter, 144dB, 1.8 / 3.3V, -40 to 85 degC, 48-Pin TQFP (PFB), Green (RoHS & no Sb/Br)", Alternate Manufacturer="Texas Instruments", Alternate PartNumber=Equivalent, Power Supply(V)="1.8, 3.3", Supplier Part Number 1=296-19740-2-ND
U8: library part CMP-0075392-3, "175-W Stereo, 350-W Mono Ultra-HD Digital-Input Class-D Amplifier with Advanced DSP Processing, DKQ0056A (SSOP-56)", Alternate Manufacturer="Texas Instruments", Alternate PartNumber=TAS3251DKQ
U9 U11 U13 U14 U31: "Single 2-Line to 1-Line Data Selector Multiplexer, DCT0008A (SSOP-8)", Alternate Manufacturer="Texas Instruments"
U10: "High Voltage 1A Step Down Switching Regulator, 10-pin LLP, Pb-Free", Manufacturer="Texas Instruments", PackageTopMarking=NS*UZXYTT*L00065B, PowerWise=N, Supplier Part Number 1=LM5010ASDTR-ND
U12: "MIXED SIGNAL MICROCONTROLLER, RHA0040B (VQFN-40)", Alternate Manufacturer="Texas Instruments", Alternate PartNumber=MSP430G2955IRHA40T
U15: "1A Low Dropout Regulator, 4-pin SOT-223, Pb-Free", Manufacturer="Texas Instruments", PackageTopMarking=XYTT*L56B, PowerWise=N, Supplier Part Number 1=LM2940IMP-12TR-ND
U16: "Buck Step Down Regulator with 3 to 17 V Input and 5 V Output, -40 to 85 degC, 8-Pin WSON (DSG), Green (RoHS & no Sb/Br)", Alternate Manufacturer="Texas Instruments", Alternate PartNumber=Equivalent, Rating=Catalog, Supplier Part Number 1=296-29898-2-ND, Switch Current Limit(Typ)(A)=1.8
U17: library part CMP-0073732-2, "Dual, 1-A, Low Noise (3.8-uVRMS), LDO Voltage Regulator, RTJ0020D (WQFN-20)", Alternate Manufacturer="Texas Instruments", Alternate PartNumber=TPS7A8801RTJT
U18 U19 U20 U21 U22 U23 U24 U25: library part SN74LVC1G125DSFR, "Single Bus Buffer Gate With 3-State Output, DSF0006A (X2SON-6)", Alternate Manufacturer="Texas Instruments"
U26: "Programmable 1-PLL VCXO Clock Synthesizer With 1.8-V, 2.5-V, and 3.3-V Outputs, PW0014A (TSSOP-14)", Alternate Manufacturer="Texas Instruments", Alternate PartNumber=CDCE913PW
